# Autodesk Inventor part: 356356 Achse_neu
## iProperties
Created: 2006-10
Part Number: 356356 Achse_neu
Material: 1.0718.07
Description: Bolzen
Document SubType Name: Modeling
Designer: OSchmidt
Density: 7.84 g/cm^3
Mass: 101.967 g
Surface Area: 52.2737 cm^2
Volume: 13.0059 cm^3
Abmessung: Rd. 12
HalbzeugNorm: DIN 671
Zweck: 266450
Author: OSchmidt
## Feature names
1. Extrusion2
2. Bohrung1 [Hole]
3. Spiegeln2 [Mirror]
